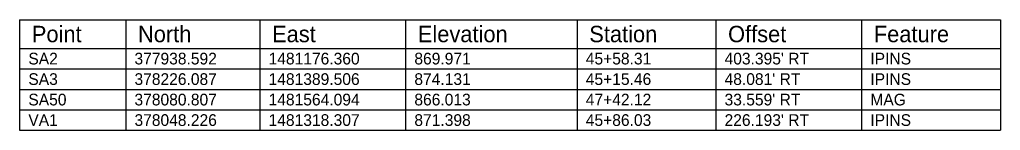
# Model space of a CAD drawing. Extents: x 1470334 to 1482043, y 378207 to 388330.
# Drawn here: x 1481622.1 to 1482042.6, y 378207 to 378254.3 of the extents above; entities that cross this region are included whole.
import ezdxf

# ---------------------------------------------------------------- set-up
doc = ezdxf.new("R2010")
doc.units = 0
doc.layers.add('Default', color=7, linetype='Continuous')

msp = doc.modelspace()

# ---------------------------------------------------------------- linework, layer by layer
at = {"layer": 'Default'}
for p, q in [((1481622.06, 378254.27), (1482042.56, 378254.27)), ((1481622.06, 378254.27), (1481622.06, 378207.02)), ((1481622.06, 378254.27), (1482042.56, 378254.27)), ((1481622.06, 378254.27), (1481622.06, 378207.02)), ((1481667.56, 378254.27), (1481667.56, 378207.02)), ((1481667.56, 378254.27), (1481667.56, 378207.02)), ((1481725.06, 378254.27), (1481725.06, 378207.02)), ((1481725.06, 378254.27), (1481725.06, 378207.02)), ((1481787.56, 378254.27), (1481787.56, 378207.02)), ((1481787.56, 378254.27), (1481787.56, 378207.02)), ((1481861.06, 378254.27), (1481861.06, 378207.02)), ((1481861.06, 378254.27), (1481861.06, 378207.02)), ((1481920.56, 378254.27), (1481920.56, 378207.02)), ((1481920.56, 378254.27), (1481920.56, 378207.02)), ((1481983.06, 378254.27), (1481983.06, 378207.02)), ((1481983.06, 378254.27), (1481983.06, 378207.02)), ((1482042.56, 378254.27), (1482042.56, 378207.02)), ((1482042.56, 378254.27), (1482042.56, 378207.02)), ((1482042.56, 378254.27), (1482042.56, 378207.02)), ((1482042.56, 378254.27), (1482042.56, 378207.02)), ((1481622.06, 378242.02), (1482042.56, 378242.02)), ((1481622.06, 378242.02), (1482042.56, 378242.02)), ((1481622.06, 378233.27), (1482042.56, 378233.27)), ((1481622.06, 378233.27), (1482042.56, 378233.27)), ((1481622.06, 378233.27), (1482042.56, 378233.27)), ((1481622.06, 378233.27), (1482042.56, 378233.27)), ((1481622.06, 378233.27), (1482042.56, 378233.27)), ((1481622.06, 378233.27), (1482042.56, 378233.27)), ((1481622.06, 378233.27), (1482042.56, 378233.27)), ((1481622.06, 378233.27), (1482042.56, 378233.27)), ((1481622.06, 378233.27), (1482042.56, 378233.27)), ((1481622.06, 378233.27), (1482042.56, 378233.27)), ((1481622.06, 378233.27), (1482042.56, 378233.27)), ((1481622.06, 378233.27), (1482042.56, 378233.27)), ((1481622.06, 378233.27), (1482042.56, 378233.27)), ((1481622.06, 378233.27), (1482042.56, 378233.27)), ((1481622.06, 378224.52), (1482042.56, 378224.52)), ((1481622.06, 378224.52), (1482042.56, 378224.52)), ((1481622.06, 378224.52), (1482042.56, 378224.52)), ((1481622.06, 378224.52), (1482042.56, 378224.52)), ((1481622.06, 378224.52), (1482042.56, 378224.52)), ((1481622.06, 378224.52), (1482042.56, 378224.52)), ((1481622.06, 378224.52), (1482042.56, 378224.52)), ((1481622.06, 378224.52), (1482042.56, 378224.52)), ((1481622.06, 378224.52), (1482042.56, 378224.52)), ((1481622.06, 378224.52), (1482042.56, 378224.52)), ((1481622.06, 378224.52), (1482042.56, 378224.52)), ((1481622.06, 378224.52), (1482042.56, 378224.52)), ((1481622.06, 378224.52), (1482042.56, 378224.52)), ((1481622.06, 378224.52), (1482042.56, 378224.52)), ((1481622.06, 378215.77), (1482042.56, 378215.77)), ((1481622.06, 378215.77), (1482042.56, 378215.77)), ((1481622.06, 378215.77), (1482042.56, 378215.77)), ((1481622.06, 378215.77), (1482042.56, 378215.77)), ((1481622.06, 378215.77), (1482042.56, 378215.77)), ((1481622.06, 378215.77), (1482042.56, 378215.77)), ((1481622.06, 378215.77), (1482042.56, 378215.77)), ((1481622.06, 378215.77), (1482042.56, 378215.77)), ((1481622.06, 378215.77), (1482042.56, 378215.77)), ((1481622.06, 378215.77), (1482042.56, 378215.77)), ((1481622.06, 378215.77), (1482042.56, 378215.77)), ((1481622.06, 378215.77), (1482042.56, 378215.77)), ((1481622.06, 378215.77), (1482042.56, 378215.77)), ((1481622.06, 378215.77), (1482042.56, 378215.77)), ((1481622.06, 378207.02), (1482042.56, 378207.02)), ((1481622.06, 378207.02), (1482042.56, 378207.02)), ((1481622.06, 378207.02), (1482042.56, 378207.02)), ((1481622.06, 378207.02), (1482042.56, 378207.02)), ((1481622.06, 378207.02), (1482042.56, 378207.02)), ((1481622.06, 378207.02), (1482042.56, 378207.02)), ((1481622.06, 378207.02), (1482042.56, 378207.02)), ((1481622.06, 378207.02), (1482042.56, 378207.02)), ((1481622.06, 378207.02), (1482042.56, 378207.02)), ((1481622.06, 378207.02), (1482042.56, 378207.02)), ((1481622.06, 378207.02), (1482042.56, 378207.02)), ((1481622.06, 378207.02), (1482042.56, 378207.02)), ((1481622.06, 378207.02), (1482042.56, 378207.02)), ((1481622.06, 378207.02), (1482042.56, 378207.02))]:
    msp.add_line(p, q, dxfattribs=at)

# ---------------------------------------------------------------- texts
for s, height, p in [('Point', 7, (1481627.31, 378244.65)), ('Point', 7, (1481627.31, 378244.65)), ('North', 7, (1481672.81, 378244.65)), ('North', 7, (1481672.81, 378244.65)), ('East', 7, (1481730.31, 378244.65)), ('East', 7, (1481730.31, 378244.65)), ('Elevation', 7, (1481792.81, 378244.65)), ('Elevation', 7, (1481792.81, 378244.65)), ('Station', 7, (1481866.31, 378244.65)), ('Station', 7, (1481866.31, 378244.65)), ('Offset', 7, (1481925.81, 378244.65)), ('Offset', 7, (1481925.81, 378244.65)), ('Feature', 7, (1481988.31, 378244.65)), ('Feature', 7, (1481988.31, 378244.65)), ('SA2', 5, (1481625.81, 378235.15)), ('SA2', 5, (1481625.81, 378235.15)), ('377938.592', 5, (1481671.31, 378235.15)), ('377938.592', 5, (1481671.31, 378235.15)), ('1481176.360', 5, (1481728.81, 378235.15)), ('1481176.360', 5, (1481728.81, 378235.15)), ('869.971', 5, (1481791.31, 378235.15)), ('869.971', 5, (1481791.31, 378235.15)), ('45+58.31', 5, (1481864.81, 378235.15)), ('45+58.31', 5, (1481864.81, 378235.15)), ("403.395' RT", 5, (1481924.31, 378235.15)), ("403.395' RT", 5, (1481924.31, 378235.15)), ('IPINS', 5, (1481986.81, 378235.15)), ('IPINS', 5, (1481986.81, 378235.15)), ('SA3', 5, (1481625.81, 378226.4)), ('SA3', 5, (1481625.81, 378226.4)), ('378226.087', 5, (1481671.31, 378226.4)), ('378226.087', 5, (1481671.31, 378226.4)), ('1481389.506', 5, (1481728.81, 378226.4)), ('1481389.506', 5, (1481728.81, 378226.4)), ('874.131', 5, (1481791.31, 378226.4)), ('874.131', 5, (1481791.31, 378226.4)), ('45+15.46', 5, (1481864.81, 378226.4)), ('45+15.46', 5, (1481864.81, 378226.4)), ("48.081' RT", 5, (1481924.31, 378226.4)), ("48.081' RT", 5, (1481924.31, 378226.4)), ('IPINS', 5, (1481986.81, 378226.4)), ('IPINS', 5, (1481986.81, 378226.4)), ('SA50', 5, (1481625.81, 378217.65)), ('SA50', 5, (1481625.81, 378217.65)), ('378080.807', 5, (1481671.31, 378217.65)), ('378080.807', 5, (1481671.31, 378217.65)), ('1481564.094', 5, (1481728.81, 378217.65)), ('1481564.094', 5, (1481728.81, 378217.65)), ('866.013', 5, (1481791.31, 378217.65)), ('866.013', 5, (1481791.31, 378217.65)), ('47+42.12', 5, (1481864.81, 378217.65)), ('47+42.12', 5, (1481864.81, 378217.65)), ("33.559' RT", 5, (1481924.31, 378217.65)), ("33.559' RT", 5, (1481924.31, 378217.65)), ('MAG', 5, (1481986.81, 378217.65)), ('MAG', 5, (1481986.81, 378217.65)), ('VA1', 5, (1481625.81, 378208.9)), ('VA1', 5, (1481625.81, 378208.9)), ('378048.226', 5, (1481671.31, 378208.9)), ('378048.226', 5, (1481671.31, 378208.9)), ('1481318.307', 5, (1481728.81, 378208.9)), ('1481318.307', 5, (1481728.81, 378208.9)), ('871.398', 5, (1481791.31, 378208.9)), ('871.398', 5, (1481791.31, 378208.9)), ('45+86.03', 5, (1481864.81, 378208.9)), ('45+86.03', 5, (1481864.81, 378208.9)), ("226.193' RT", 5, (1481924.31, 378208.9)), ("226.193' RT", 5, (1481924.31, 378208.9)), ('IPINS', 5, (1481986.81, 378208.9)), ('IPINS', 5, (1481986.81, 378208.9))]:
    msp.add_text(s, height=height, dxfattribs=at).set_placement(p)

doc.saveas('drawing.dxf')
